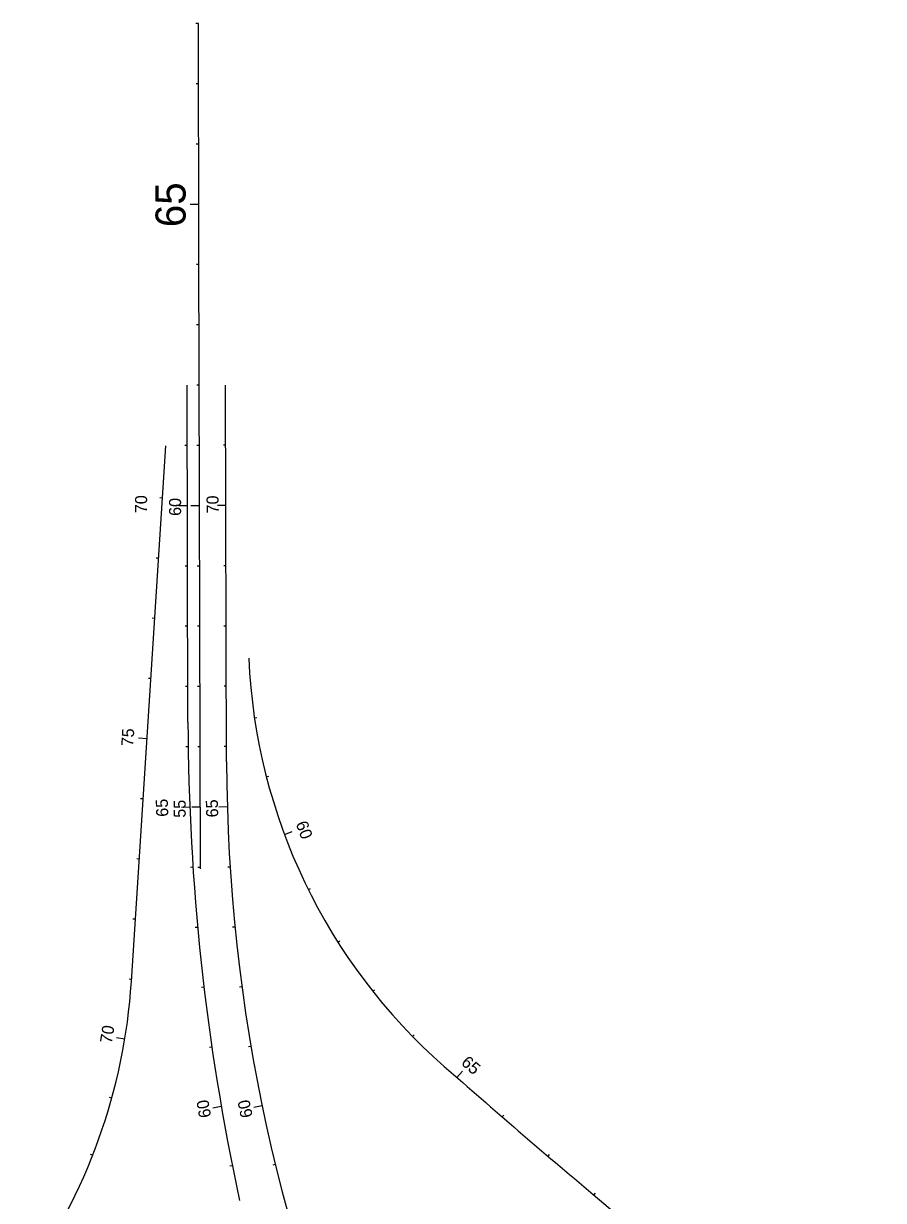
# Model space of a CAD drawing. Extents: x 448091 to 665917, y 1461380 to 1587607.
# Drawn here: x 556258 to 557684, y 1498016 to 1499969 of the extents above; entities that cross this region are included whole.
import ezdxf

# ---------------------------------------------------------------- set-up
doc = ezdxf.new("R2010")
doc.units = 0
doc.layers.add('TextShtNo', color=7, linetype='Continuous')
doc.layers.add('TextTitle', color=7, linetype='Continuous')

msp = doc.modelspace()

# ---------------------------------------------------------------- linework, layer by layer
at = {"layer": 'TextShtNo'}
for p, q in [((556548.5, 1499591.5), (556547.9, 1499968.7)), ((556551.2, 1498566.2), (556548.5, 1499591.5)), ((556530.6, 1498809.9), (556529.1, 1499368.6)), ((556594.7, 1498743.6), (556593.1, 1499368.8)), ((556436.7, 1498379.2), (556493.6, 1499268)), ((557202.7, 1498026.2), (557684.4, 1497620.5))]:
    msp.add_line(p, q, dxfattribs=at)
for centre, radius, start, end in [((557585.6, 1498956.3), 954.9, 182.4447, 228.7262), ((560350.1, 1498819.9), 3819.5, 180.15, 192.1472), ((559459.4, 1498751.1), 2864.7, 180.15, 204.4403), ((555483.7, 1498440.1), 954.9, 324.1545, 356.3397), ((567510.2, 1510263.7), 16000, 228.72624, 229.8929)]:
    msp.add_arc(centre, radius, start, end, dxfattribs=at)
at = {"layer": 'TextTitle'}
for p, q in [((556547.9, 1499968.7), (556543.9, 1499968.7)), ((556548, 1499868.7), (556544, 1499868.7)), ((556548.2, 1499768.7), (556544.2, 1499768.7)), ((556548.4, 1499668.7), (556534.4, 1499668.7)), ((556548.6, 1499568.7), (556544.6, 1499568.7)), ((556548.8, 1499468.7), (556544.8, 1499468.7)), ((556549.1, 1499368.7), (556545.1, 1499368.7)), ((556529.4, 1499268.7), (556525.4, 1499268.7)), ((556549.4, 1499268.7), (556545.4, 1499268.7)), ((556593.4, 1499269.2), (556589.4, 1499269.2)), ((556488, 1499181.3), (556484, 1499181.6)), ((556529.6, 1499168.7), (556515.6, 1499168.7)), ((556549.6, 1499168.7), (556535.6, 1499168.7)), ((556593.6, 1499169.2), (556579.6, 1499169.2)), ((556481.6, 1499081.5), (556477.6, 1499081.8)), ((556529.9, 1499068.7), (556525.9, 1499068.7)), ((556549.9, 1499068.7), (556545.9, 1499068.7)), ((556593.9, 1499069.2), (556589.9, 1499069.2)), ((556475.2, 1498981.7), (556471.2, 1498982)), ((556530.2, 1498968.7), (556526.2, 1498968.7)), ((556550.2, 1498968.7), (556546.2, 1498968.7)), ((556594.2, 1498969.2), (556590.2, 1498969.2)), ((556468.9, 1498881.9), (556464.9, 1498882.2)), ((556530.4, 1498868.7), (556526.4, 1498868.7)), ((556550.4, 1498868.7), (556546.4, 1498868.7)), ((556594.4, 1498869.2), (556590.4, 1498869.2)), ((556640.9, 1498816.9), (556644.8, 1498817.5)), ((556462.5, 1498782.1), (556448.5, 1498783)), ((556530.9, 1498768.8), (556526.9, 1498768.7)), ((556550.7, 1498768.7), (556546.7, 1498768.7)), ((556594.7, 1498769.2), (556590.7, 1498769.2)), ((556660.6, 1498718.9), (556664.5, 1498719.9)), ((556456.1, 1498682.3), (556452.1, 1498682.6)), ((556533.5, 1498668.8), (556519.6, 1498668.2)), ((556550.9, 1498668.7), (556536.9, 1498668.7)), ((556595.9, 1498669.2), (556581.9, 1498668.8)), ((556690.5, 1498623.5), (556703.6, 1498628.4)), ((556449.7, 1498582.5), (556445.7, 1498582.8)), ((556538.8, 1498568.9), (556534.8, 1498568.7)), ((556551.2, 1498568.7), (556547.2, 1498568.7)), ((556600.5, 1498569.3), (556596.5, 1498569.1)), ((556730.2, 1498531.8), (556733.8, 1498533.6)), ((556443.3, 1498482.7), (556439.3, 1498483)), ((556546.7, 1498469.2), (556542.7, 1498468.9)), ((556608.6, 1498469.6), (556604.6, 1498469.3)), ((556779.3, 1498444.7), (556782.7, 1498446.8)), ((556436.9, 1498382.9), (556432.9, 1498383.2)), ((556557.2, 1498369.8), (556553.2, 1498369.3)), ((556620.2, 1498370.3), (556616.2, 1498369.8)), ((556837.2, 1498363.2), (556840.3, 1498365.7)), ((556425.7, 1498283.6), (556411.9, 1498285.9)), ((556903.3, 1498288.2), (556906.1, 1498291)), ((556570.3, 1498270.7), (556566.3, 1498270.1)), ((556635.2, 1498271.5), (556631.2, 1498270.8)), ((556976.6, 1498220.3), (556985.8, 1498230.8)), ((556404.2, 1498186), (556400.3, 1498187.1)), ((556585.9, 1498171.9), (556572.1, 1498169.5)), ((556653.6, 1498173.2), (556639.9, 1498170.4)), ((557052.1, 1498154.7), (557054.7, 1498157.7)), ((556372.6, 1498091.2), (556368.9, 1498092.6)), ((557128, 1498089.6), (557130.6, 1498092.6)), ((556604.2, 1498073.6), (556600.3, 1498072.8)), ((556675.5, 1498075.6), (556671.6, 1498074.7)), ((557204.2, 1498024.9), (557206.8, 1498028))]:
    msp.add_line(p, q, dxfattribs=at)

# ---------------------------------------------------------------- texts
for s, height, rotation, p in [('65', 50, 90.1022, (556526.7, 1499630.9)), ('70', 20, 90.15, (556462.8, 1499156.4)), ('60', 20, 90.15, (556519.2, 1499151.9)), ('70', 20, 90.15, (556581.4, 1499156)), ('75', 20, 86.3397, (556439.7, 1498769.1)), ('65', 20, 92.2669, (556498.1, 1498653.1)), ('55', 20, 90.15, (556526.8, 1498651.1)), ('65', 20, 91.6373, (556580.9, 1498652)), ('60', 20, 290.3967, (556709, 1498641.4)), ('70', 20, 80.5659, (556404, 1498275.6)), ('65', 20, 318.8259, (556982.4, 1498242.9)), ('60', 20, 99.7672, (556569.2, 1498155.1)), ('60', 20, 101.6378, (556638.2, 1498155.5))]:
    msp.add_text(s, height=height, rotation=rotation, dxfattribs=at).set_placement(p)

doc.saveas('drawing.dxf')
